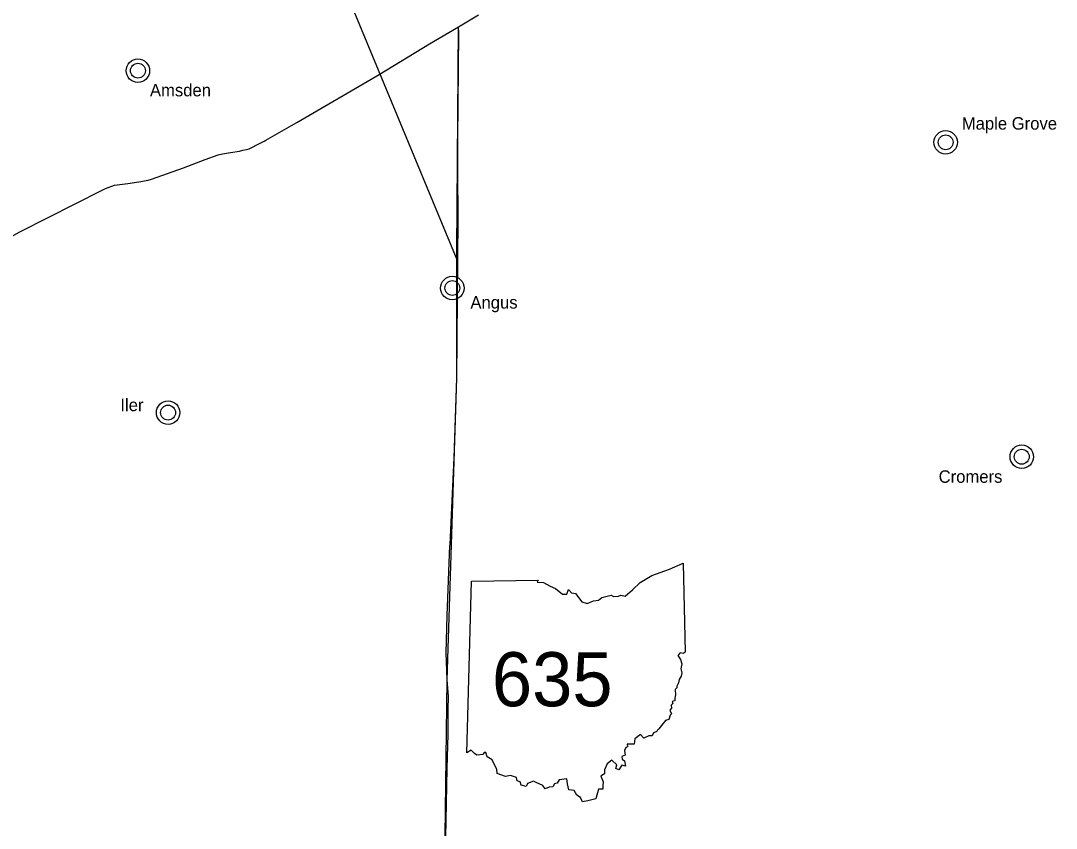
# Model space of a CAD drawing. Extents: x 0 to 882, y 0 to 440.
# Drawn here: x 198.3 to 285, y 237.6 to 305.2 of the extents above; entities that cross this region are included whole.
import ezdxf

# ---------------------------------------------------------------- set-up
doc = ezdxf.new("R2010")
doc.units = 0
for name, color, linetype in [('DV_X_Corp_Line', 7, 'Continuous'), ('GM_X_State_Route', 7, 'Continuous'), ('PV_P_Text', 7, 'Continuous'), ('RD_P_Fence', 7, 'Continuous'), ('SH_Data', 7, 'Continuous')]:
    doc.layers.add(name, color=color, linetype=linetype)

msp = doc.modelspace()

# ---------------------------------------------------------------- linework, layer by layer
at = {"layer": 'DV_X_Corp_Line'}
for centre, radius in [((208.14, 300.991), 0.982), ((208.14, 300.991), 0.623), ((275.777, 294.998), 0.982), ((275.777, 294.998), 0.623), ((234.467, 282.801), 0.982), ((234.467, 282.801), 0.623), ((210.666, 272.374), 0.982), ((210.666, 272.374), 0.623), ((282.152, 268.683), 0.982), ((282.152, 268.683), 0.623)]:
    msp.add_circle(centre, radius, dxfattribs=at)
at = {"layer": 'GM_X_State_Route'}
for points in [[(218.844, 295.171), (218.848, 295.173), (221.012, 296.408), (221.457, 296.666), (228.355, 300.668), (232.562, 303.24), (234.975, 304.675), (236.099, 305.327), (236.385, 305.51), (236.655, 305.674)], [(234.935, 295.188), (234.935, 295.282), (235.001, 304.125), (234.975, 304.675)], [(205.208, 291.015), (205.435, 291.125), (206.185, 291.412), (207.306, 291.552), (208.203, 291.683), (208.996, 291.832), (209.288, 291.914), (211.948, 292.861), (213.784, 293.567), (214.848, 293.95), (215.231, 294.023), (215.893, 294.151), (216.653, 294.261), (216.933, 294.327), (217.237, 294.388), (217.456, 294.443), (217.687, 294.559), (218.143, 294.811), (218.72, 295.1), (218.844, 295.171)], [(234.939, 292.552), (234.935, 295.188)], [(234.273, 261.266), (234.275, 261.309), (234.367, 263.197), (234.631, 268.583), (234.841, 275.261), (234.944, 288.599), (234.939, 292.552)], [(189.263, 277.363), (189.489, 277.512), (189.732, 277.691), (189.947, 277.839), (190.29, 278.09), (190.741, 278.519), (191.048, 278.891), (191.692, 280.029), (192.303, 281.41), (192.811, 282.533), (193.04, 283.019), (193.336, 283.613), (193.665, 284.279), (194.051, 284.865), (194.384, 285.2), (194.649, 285.462), (194.946, 285.691), (198.239, 287.516), (205.208, 291.015)], [(233.741, 226.08), (233.863, 233.932), (234.036, 242.59), (234.109, 245.454), (234.128, 247.531), (234.155, 248.62), (234.037, 250.015), (233.951, 252.278), (234.044, 255.383), (234.273, 261.266)]]:
    msp.add_lwpolyline(points, dxfattribs=at)
at = {"layer": 'PV_P_Text'}
msp.add_line((235.677, 243.899), (236.079, 258.262), dxfattribs=at)
msp.add_line((235.677, 243.899), (236.079, 258.262), dxfattribs=at)
for points in [[(236.079, 258.262), (241.652, 258.355), (241.565, 258.181), (242.091, 258.145), (242.649, 257.838), (243.121, 257.645), (243.699, 257.188), (244.045, 257.193), (244.191, 257.567), (244.456, 257.279), (244.77, 257.227), (245.313, 256.539), (245.762, 256.391), (246.299, 256.626), (246.701, 256.665), (246.994, 256.898), (247.759, 257.097), (247.972, 256.978), (248.377, 257.002), (248.58, 257.09), (248.934, 257.011), (249.555, 257.533), (250.195, 258.149), (251.179, 258.73), (252.649, 259.28), (253.812, 259.773), (253.98, 252.319)], [(236.079, 258.262), (241.652, 258.355), (241.565, 258.181), (242.091, 258.145), (242.649, 257.838), (243.121, 257.645), (243.699, 257.188), (244.045, 257.193), (244.191, 257.567), (244.456, 257.279), (244.77, 257.227), (245.313, 256.539), (245.762, 256.391), (246.299, 256.626), (246.701, 256.665), (246.994, 256.898), (247.759, 257.097), (247.972, 256.978), (248.377, 257.002), (248.58, 257.09), (248.934, 257.011), (249.555, 257.533), (250.195, 258.149), (251.179, 258.73), (252.649, 259.28), (253.812, 259.773), (253.98, 252.319)], [(253.98, 252.319), (253.808, 252.215), (253.541, 252.264), (253.362, 252.055), (253.584, 251.706), (253.689, 251.338), (253.596, 250.932), (253.687, 250.597), (253.625, 250.316), (253.457, 250.037), (253.399, 249.771), (253.257, 249.491), (253.268, 249.334), (253.132, 249.21), (253.157, 248.744), (253.088, 248.485), (253.112, 248.262), (252.891, 248.204), (252.942, 248.02), (252.802, 247.878), (252.831, 247.633), (252.672, 247.477), (252.827, 247.164), (252.703, 247.065), (252.6, 246.685), (252.317, 246.608), (251.75, 245.912), (251.55, 245.649), (251.325, 245.584), (251.202, 245.313), (250.925, 245.312), (250.506, 245.125), (250.236, 245.447), (249.762, 245.06), (249.707, 244.612), (249.107, 244.626), (249.131, 244.4), (248.997, 244.334), (248.875, 244.107), (248.946, 243.704), (248.665, 243.601), (248.699, 243.367), (248.879, 243.224), (248.959, 242.777), (248.661, 242.867), (248.416, 242.49), (248.165, 242.579), (248.247, 242.898), (247.823, 243.282), (247.421, 242.975), (247.212, 242.483), (247.209, 242.153), (246.91, 241.953), (247.102, 241.486), (247.067, 241.164), (247.073, 240.858), (246.699, 240.869), (246.472, 240.045)], [(253.98, 252.319), (253.808, 252.215), (253.541, 252.264), (253.362, 252.055), (253.584, 251.706), (253.689, 251.338), (253.596, 250.932), (253.687, 250.597), (253.625, 250.316), (253.457, 250.037), (253.399, 249.771), (253.257, 249.491), (253.268, 249.334), (253.132, 249.21), (253.157, 248.744), (253.088, 248.485), (253.112, 248.262), (252.891, 248.204), (252.942, 248.02), (252.802, 247.878), (252.831, 247.633), (252.672, 247.477), (252.827, 247.164), (252.703, 247.065), (252.6, 246.685), (252.317, 246.608), (251.75, 245.912), (251.55, 245.649), (251.325, 245.584), (251.202, 245.313), (250.925, 245.312), (250.506, 245.125), (250.236, 245.447), (249.762, 245.06), (249.707, 244.612), (249.107, 244.626), (249.131, 244.4), (248.997, 244.334), (248.875, 244.107), (248.946, 243.704), (248.665, 243.601), (248.699, 243.367), (248.879, 243.224), (248.959, 242.777), (248.661, 242.867), (248.416, 242.49), (248.165, 242.579), (248.247, 242.898), (247.823, 243.282), (247.421, 242.975), (247.212, 242.483), (247.209, 242.153), (246.91, 241.953), (247.102, 241.486), (247.067, 241.164), (247.073, 240.858), (246.699, 240.869), (246.472, 240.045)], [(246.472, 240.045), (245.822, 239.887), (245.37, 239.793), (245.211, 240.167), (244.888, 240.365), (244.678, 240.742), (244.215, 240.793), (244.105, 241.311), (244.053, 241.731), (243.419, 241.628), (243.245, 241.371), (243.02, 241.302), (242.89, 241.043), (242.583, 241.021), (242.255, 240.899), (242.04, 241.153), (241.501, 241.408), (241.259, 241.539), (240.752, 241.335), (240.644, 241.093), (240.241, 241.2), (240.147, 241.47), (239.903, 241.551), (239.849, 241.837), (239.327, 241.989), (238.928, 241.928), (238.225, 242.159), (238.182, 242.535), (237.943, 242.994), (237.817, 243.312), (237.373, 243.555), (237.283, 243.934), (237.14, 243.923), (237.01, 243.769), (236.517, 243.698), (236.319, 243.853), (236.043, 244.117), (235.677, 243.899)], [(246.472, 240.045), (245.822, 239.887), (245.37, 239.793), (245.211, 240.167), (244.888, 240.365), (244.678, 240.742), (244.215, 240.793), (244.105, 241.311), (244.053, 241.731), (243.419, 241.628), (243.245, 241.371), (243.02, 241.302), (242.89, 241.043), (242.583, 241.021), (242.255, 240.899), (242.04, 241.153), (241.501, 241.408), (241.259, 241.539), (240.752, 241.335), (240.644, 241.093), (240.241, 241.2), (240.147, 241.47), (239.903, 241.551), (239.849, 241.837), (239.327, 241.989), (238.928, 241.928), (238.225, 242.159), (238.182, 242.535), (237.943, 242.994), (237.817, 243.312), (237.373, 243.555), (237.283, 243.934), (237.14, 243.923), (237.01, 243.769), (236.517, 243.698), (236.319, 243.853), (236.043, 244.117), (235.677, 243.899)]]:
    msp.add_lwpolyline(points, dxfattribs=at)
at = {"layer": 'RD_P_Fence'}
msp.add_lwpolyline([(233.741, 226.08), (234.037, 250.015), (234.841, 275.261), (234.841, 285.964), (234.975, 304.675)], dxfattribs=at)
at = {"layer": 'SH_Data'}
msp.add_line((209.452, 346.401), (234.841, 285.177), dxfattribs=at)

# ---------------------------------------------------------------- texts
at = {"layer": 'DV_X_Corp_Line'}
for s, height, p in [('Amsden', 1.0417, (209.146, 298.844)), ('Maple Grove', 1.04167, (277.132, 296.059)), ('Angus', 1.0417, (235.982, 281.081)), ('Iler', 1.0417, (206.673, 272.495)), ('Cromers', 1.0417, (275.192, 266.501))]:
    msp.add_text(s, height=height, rotation=0.00001, dxfattribs=at).set_placement(p)
at = {"layer": 'PV_P_Text'}
msp.add_text('635', height=4.5281, dxfattribs=at).set_placement((237.784, 247.795))

doc.saveas('drawing.dxf')
